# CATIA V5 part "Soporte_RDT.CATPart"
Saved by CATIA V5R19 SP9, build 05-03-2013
Part number: Soporte_RDT
Bounding box of the stored display mesh (mm): x -100 to 100, y 0 to 160, z 0 to 56
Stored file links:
  D:\PROGRAMACION\PROYECTOS\DEFCON\CAD\Soporte_RDT.CATPart
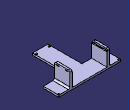
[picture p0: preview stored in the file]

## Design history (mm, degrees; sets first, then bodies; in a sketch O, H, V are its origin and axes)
Set1
  DatumCurve1 to DatumCurve4
Body1 (main body)
  Sketch1 on xy-plane, origin (0, 0, 0), H (1, 0, 0), V (0, 1, 0)
    line L1 (-100, 160) -> (-100, 110)
    line L2 (-100, 110) -> (-25, 110)
    line L3 (-25, 110) -> (-25, 0)
    line L4 (-25, 0) -> (25, 0)
    line L5 (25, 0) -> (25, 110)
    point P6 (25, 110)
    line L6 (25, 110) -> (100, 110)
    line L7 (100, 110) -> (100, 160)
    line L8 (100, 160) -> (-100, 160)
    axis line L9 (0, 93) -> (0, -79)
    point P9 (0, 93)
    length L8 = 200
    length L4 = 50
    length L1 = 50
    length L3 = 110
    vertical: L1 V, L3 V, L5 V, L7 V, L9 V
    horizontal: L2 H, L4 H, L6 H, L8 H
    coincidence: P6 L2, P9 V, L4 H
    symmetry: L3 L5 L9, L1 L7 L9
  Pad1: profile Sketch1, direction (0, 0, 1), length 6
  Sketch2 on start face of Pad1, origin (0, 0, 0), H (1, 0, 0), V (0, -1, 0)
    projected circle E1 centre (96, -156) radius 1.7 from edge of DatumCurve1
    projected circle E2 centre (-96, -156) radius 1.7 from edge of DatumCurve2
    projected circle E3 centre (-21, -9) radius 1.7 from edge of DatumCurve3
    projected circle E4 centre (21, -9) radius 1.7 from edge of DatumCurve4
  Pocket1: profile Sketch2, direction (0, 0, 1), through (limit type 3)
  Sketch3 on end face of Pad1, origin (0, 0, 6), H (1, 0, 0), V (0, 1, 0)
    circle A1 centre (-21, 9) radius 3
    circle A2 centre (21, 9) radius 3
    reference projected circle E1 centre (-21, 9) radius 1.7 from edge [end face of Pad1 | face of Pocket1 from Sketch2.E3]
    reference projected circle E2 centre (21, 9) radius 1.7 from edge [end face of Pad1 | face of Pocket1 from Sketch2.E4]
    radius A2 = 3
    radius A1 = 3
    concentricity: E1 A1, E2 A2
  Pocket2: profile Sketch3, direction (0, 0, -1), length 3
  Sketch4 on end face of Pad1, origin (0, 0, 6), H (1, 0, 0), V (0, 1, 0)
    axis line L1 (0, 180) -> (0, -24)
    point P1 (0, 180)
    point P3 (-64, 160)
    line L2 (-64, 160) -> (-56, 160)
    line L3 (-56, 160) -> (-56, 110)
    line L4 (-56, 110) -> (-64, 110)
    line L5 (-64, 110) -> (-64, 160)
    point P4 (-56, 160)
    point P5 (-56, 110)
    point P6 (-64, 110)
    reference projected line E1 (100, 160) -> (-100, 160) from edge [start face of Pad1 | face of Pad1 from Sketch1.L8]
    reference projected line E2 (-100, 110) -> (-25, 110) from edge [start face of Pad1 | face of Pad1 from Sketch1.L2]
    point P7 (64, 160)
    point P8 (56, 160)
    point P9 (56, 110)
    point P10 (64, 110)
    line L6 (64, 160) -> (56, 160)
    line L7 (56, 160) -> (56, 110)
    line L8 (56, 110) -> (64, 110)
    line L9 (64, 110) -> (64, 160)
    length L4 = 8
    distance L3 L1 = 56
    coincidence: P1 V, L2 E1, L4 E2
    vertical: L1 V, L3 V, L5 V
    horizontal: L2 H, L4 H
    symmetry: P3 P7 L1, P4 P8 L1, P5 P9 L1, P6 P10 L1, L2 L6 L1, L3 L7 L1, L4 L8 L1, L5 L9 L1
  Pad2: profile Sketch4, direction (0, 0, 1), length 50
  Sketch5 on face of Pad2 from Sketch4.L5, origin (-64, 0, 0), H (0, -1, 0), V (0, 0, 1)
    axis line L1 (-135, 89) -> (-135, -20)
    reference projected line E1 (-160, 6) -> (-160, 56) from edge [face of Pad2 from Sketch4.L5 | face of Pad2]
    reference projected line E2 (-110, 6) -> (-110, 56) from edge [face of Pad2 | face of Pad2 from Sketch4.L5]
    point P3 (-155, 52)
    line L2 (-155, 52) -> (-145, 52)
    line L3 (-145, 52) -> (-145, 50)
    line L4 (-145, 50) -> (-155, 50)
    line L5 (-155, 50) -> (-155, 52)
    point P4 (-145, 52)
    point P5 (-145, 50)
    point P6 (-155, 50)
    reference projected line E3 (-160, 56) -> (-110, 56) from edge [face of Pad2 from Sketch4.L5 | end face of Pad2]
    point P7 (-115, 52)
    point P8 (-125, 52)
    point P9 (-125, 50)
    point P10 (-115, 50)
    line L6 (-115, 52) -> (-125, 52)
    line L7 (-125, 52) -> (-125, 50)
    line L8 (-125, 50) -> (-115, 50)
    line L9 (-115, 50) -> (-115, 52)
    distance L2 E3 = 4
    length L2 = 10
    length L5 = 2
    distance L3 L1 = 10
    vertical: L1 V, L3 V, L5 V
    symmetry: E1 E2 L1, P3 P7 L1, P4 P8 L1, P5 P9 L1, P6 P10 L1, L2 L6 L1, L3 L7 L1, L4 L8 L1, L5 L9 L1
    horizontal: L2 H, L4 H
  Pocket3: profile Sketch5, direction (1, 0, 0), through (limit type 3)
  Sketch6 on face of Pad2 from Sketch4.L3, origin (-56, 0, 0), H (0, 1, 0), V (0, 0, 1)
    line L1 (110, 56) -> (160, 56)
    line L2 (160, 56) -> (160, 50)
    line L3 (160, 50) -> (110, 50)
    line L4 (110, 50) -> (110, 56)
    reference projected line E1 (110, 56) -> (160, 56) from edge [face of Pad2 from Sketch4.L3 | end face of Pad2]
    reference projected line E2 (110, 6) -> (110, 56) from edge [face of Pad2 from Sketch4.L3 | face of Pad2]
    reference projected line E3 (160, 6) -> (160, 56) from edge [face of Pad2 | face of Pad2 from Sketch4.L3]
    length L4 = 6
    horizontal: L1 H, L3 H
    vertical: L2 V, L4 V
    coincidence: L1 E1, L4 E2, L2 E3
  Pocket4: profile Sketch6, direction (-1, 0, 0), length 1.5
  Sketch7 on face of Pad2 from Sketch4.L7, origin (56, 0, 0), H (0, -1, 0), V (0, 0, 1)
    line L1 (-160, 56) -> (-110, 56)
    line L2 (-110, 56) -> (-110, 50)
    line L3 (-110, 50) -> (-160, 50)
    line L4 (-160, 50) -> (-160, 56)
    reference projected line E1 (-160, 56) -> (-110, 56) from edge [face of Pad2 from Sketch4.L7 | end face of Pad2]
    reference projected line E2 (-160, 6) -> (-160, 56) from edge [face of Pad2 from Sketch4.L7 | face of Pad2]
    reference projected line E3 (-110, 6) -> (-110, 56) from edge [face of Pad2 | face of Pad2 from Sketch4.L7]
    length L4 = 6
    horizontal: L1 H, L3 H
    vertical: L2 V, L4 V
    coincidence: L1 E1, L4 E2, L2 E3
  Pocket5: profile Sketch7, direction (1, 0, 0), length 1.5
  Fillet1: radius 1.5, on edge [face of Pad2 from Sketch4.L3 | face of Pocket4]
  Fillet2: radius 1.5, on edge [face of Pad2 from Sketch4.L7 | face of Pocket5]
  Fillet3: radius 5, on edge [end face of Pad1 | face of Pad2 from Sketch4.L5]
  Fillet4: radius 5, on edge [end face of Pad1 | face of Pad2 from Sketch4.L9]
  Fillet5: radius 5, on edge [face of Pad2 | end face of Pad2] (x4)
  Fillet6: radius 1.5, on edge [face of Fillet1 | end face of Pocket4] (x3)
  Fillet7: radius 1.5, on edge [face of Fillet2 | end face of Pocket5] (x3)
